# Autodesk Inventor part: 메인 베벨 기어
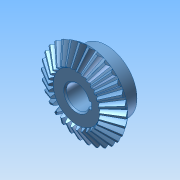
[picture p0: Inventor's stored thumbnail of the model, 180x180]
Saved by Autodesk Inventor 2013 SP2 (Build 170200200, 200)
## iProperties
Created: 2026-07
Part Number: 메인 베벨 기어
Material: Generic
Document SubType Name: Modeling
Designer: a
Density: 1 g/cm^3
Author: a
변환 표준: STEP AP214IS
전처리기: Build: 200, Release: 2013 SP2 Update 6 - Date: Thu 07/17/2014
전송 단위: 밀리미터
불확실성: 0.01
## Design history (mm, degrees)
node "메인 베벨기어1"
body "Solid1"
node "기준1"
